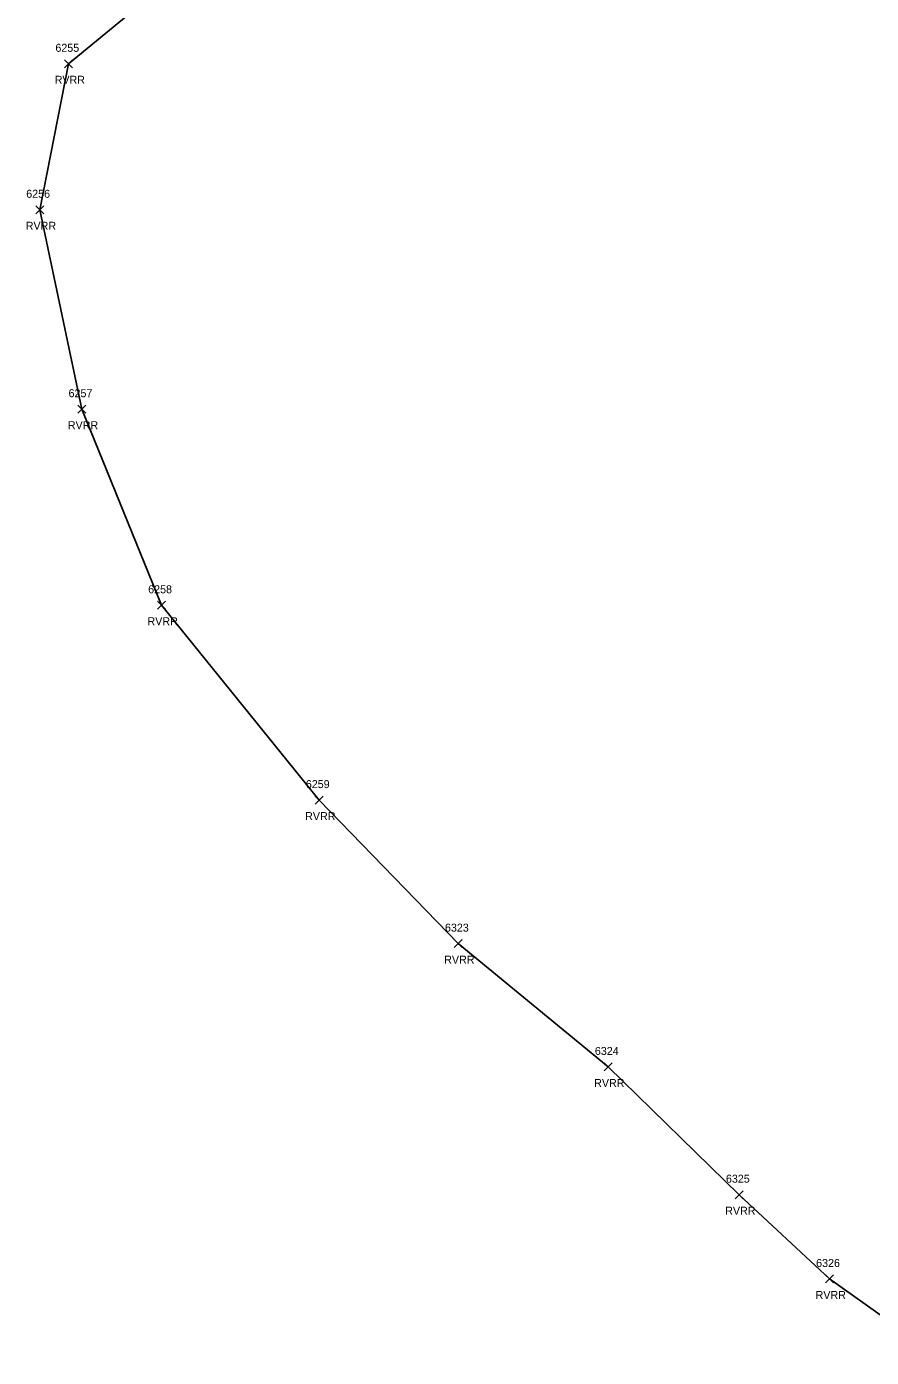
# Model space of a CAD drawing. Extents: x 1462668 to 1465147, y 550359 to 557351.
# Drawn here: x 1464698.9 to 1464910, y 551059.3 to 551391.8 of the extents above; entities that cross this region are included whole.
import ezdxf

# ---------------------------------------------------------------- set-up
doc = ezdxf.new("R2010")
doc.units = 0
for name, color, linetype in [('L_A', 7, 'Continuous'), ('L_I', 7, 'Continuous'), ('L_TIC', 7, 'Continuous'), ('LAWE', 7, 'Continuous')]:
    doc.layers.add(name, color=color, linetype=linetype)

msp = doc.modelspace()

# ---------------------------------------------------------------- linework, layer by layer
at = {"layer": 'L_TIC'}
for points in [[(1464708.4, 551381.55), (1464710.4, 551383.55)], [(1464710.4, 551381.55), (1464708.4, 551383.55)], [(1464701.17, 551345.07), (1464703.17, 551347.07)], [(1464703.17, 551345.07), (1464701.17, 551347.07)], [(1464711.68, 551295.23), (1464713.68, 551297.23)], [(1464713.68, 551295.23), (1464711.68, 551297.23)], [(1464731.59, 551246.23), (1464733.59, 551248.23)], [(1464733.59, 551246.23), (1464731.59, 551248.23)], [(1464770.98, 551197.54), (1464772.98, 551199.54)], [(1464772.98, 551197.54), (1464770.98, 551199.54)], [(1464805.74, 551161.67), (1464807.74, 551163.67)], [(1464807.74, 551161.67), (1464805.74, 551163.67)], [(1464843.21, 551130.85), (1464845.21, 551132.85)], [(1464845.21, 551130.85), (1464843.21, 551132.85)], [(1464875.96, 551098.93), (1464877.96, 551100.93)], [(1464877.96, 551098.93), (1464875.96, 551100.93)], [(1464898.55, 551077.86), (1464900.55, 551079.86)], [(1464900.55, 551077.86), (1464898.55, 551079.86)]]:
    msp.add_lwpolyline(points, dxfattribs=at)
at = {"layer": 'LAWE'}
msp.add_lwpolyline([(1464886.95, 551593.62), (1464873.85, 551575.88), (1464862.96, 551556.44), (1464846.29, 551527.15), (1464819.57, 551497.26), (1464787.42, 551463.7), (1464767.48, 551428.85), (1464746.2, 551412.84), (1464709.4, 551382.55), (1464702.17, 551346.07), (1464712.68, 551296.23), (1464732.59, 551247.23), (1464771.98, 551198.54), (1464806.74, 551162.67), (1464844.21, 551131.85), (1464876.96, 551099.93), (1464899.55, 551078.86), (1464923.7, 551061.7), (1464947.12, 551042.98)], dxfattribs=at)

# ---------------------------------------------------------------- texts
at = {"layer": 'L_A'}
for p in [(1464705.91, 551377.55), (1464698.68, 551341.07), (1464709.2, 551291.23), (1464729.1, 551242.23), (1464768.5, 551193.54), (1464803.25, 551157.67), (1464840.72, 551126.85), (1464873.47, 551094.93), (1464896.06, 551073.86)]:
    msp.add_text('RVRR', height=2, dxfattribs=at).set_placement(p)
at = {"layer": 'L_I'}
for s, p in [('6255', (1464706.09, 551385.55)), ('6256', (1464698.8, 551349.07)), ('6257', (1464709.38, 551299.23)), ('6258', (1464729.28, 551250.23)), ('6259', (1464768.67, 551201.54)), ('6323', (1464803.44, 551165.67)), ('6324', (1464840.9, 551134.85)), ('6325', (1464873.65, 551102.93)), ('6326', (1464896.19, 551081.86))]:
    msp.add_text(s, height=2, dxfattribs=at).set_placement(p)

doc.saveas('drawing.dxf')
